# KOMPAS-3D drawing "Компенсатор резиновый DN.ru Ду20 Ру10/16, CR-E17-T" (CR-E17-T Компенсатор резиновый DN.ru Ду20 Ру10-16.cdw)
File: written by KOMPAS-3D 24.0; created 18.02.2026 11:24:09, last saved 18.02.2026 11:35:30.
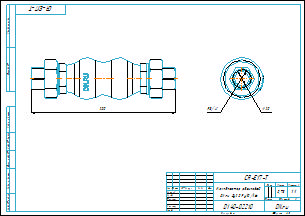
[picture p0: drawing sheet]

Document properties: Типовые: Типовые; Автор: DN.RU; Форматы листов документа: A3; Полное имя файла: CR-E17-T Компенсатор резиновый DN.ru Ду20 Ру10-16.m3d; Масса: 0.73; Наименование: Компенсатор резиновый DN.ru Ду20 Ру10/16; Количество листов документа: 1; Комментарий: D140-02210; Примечание: D140-02210

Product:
- Body: Твердое тело1  | qty 1
    Масса: 1.995832
- Part/product: Компенсатор резиновый DN.ru Ду20 Ру10/16  | designation CR-E17-T
    Масса: 0.73
    Раздел спецификации: Прочие изделия
    Форматы листов документа: A3
    Комментарий: D140-02210
    Примечание: D140-02210
    additional columns: Типовые

Views: Вид 1, Справа, Проекционный вид 2
Referenced files in D:\Работа\Компенсаторы\CR-Е17-T Компенсатор резиновый DN.ru Ду15-80\DN20\: CR-E17-T Компенсатор резиновый DN.ru Ду20 Ру10-16.m3d, CR-E17-T Компенсатор резиновый DN.ru Ду20 Ру10-16.cdw
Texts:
  Линейный размер
  CR-E17-T
  Диаметральный размер
  Компенсатор резиновый
  DN.ru Ду20 Ру10/16
  Твердое тело1
  Компенсатор резиновый DN.ru Ду20 Ру10/16
  CR-E17-T Компенсатор резиновый DN.ru Ду20 Ру10/16
Dimensions and other numbers on the sheet: 0; 3; 2; 4; 200; 20; 1:1; 1; 0,73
